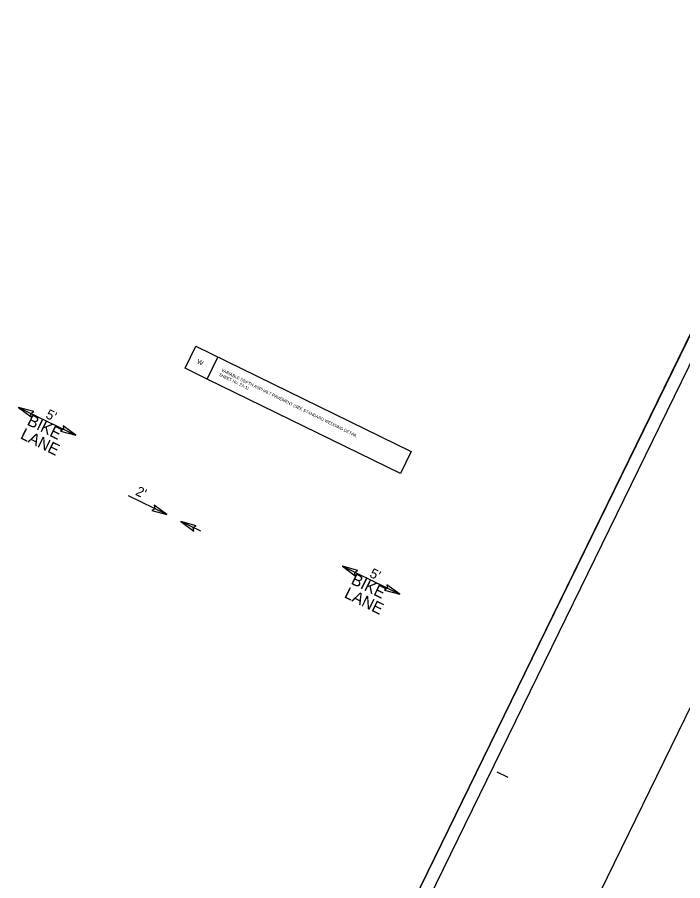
# Model space of a CAD drawing. Extents: x 1518247 to 1523638, y 635234 to 639927.
# Drawn here: x 1520564 to 1521243, y 639046 to 639927 of the extents above; entities that cross this region are included whole.
import ezdxf

# ---------------------------------------------------------------- set-up
doc = ezdxf.new("R2010")
doc.units = 0
for name, color, linetype in [('Default', 7, 'Continuous'), ('Prop Dimension', 7, 'Continuous'), ('Prop Pavement Schedule Description CELL', 7, 'Continuous'), ('Prop Shade Light', 7, 'Continuous'), ('Sheet Cutting Line CELL', 7, 'Continuous'), ('Sheet Plot Border Inside CELL', 7, 'Continuous'), ('Sheet Plot Border Outside CELL', 7, 'Continuous'), ('Sheet Typical CELL', 7, 'Continuous')]:
    doc.layers.add(name, color=color, linetype=linetype)

# ---------------------------------------------------------------- blocks, each defined once
blk = doc.blocks.new('TERMINATOR')
at = {"layer": 'Prop Shade Light'}
blk.add_lwpolyline([(-0.469, 0.081), (0, 0), (-0.471, -0.083), (-0.411, 0)], close=True, dxfattribs=at)

msp = doc.modelspace()

# ---------------------------------------------------------------- linework, layer by layer
at = {"layer": 'Default'}
msp.add_lwpolyline([(1522438.02, 638198.63), (1520925.25, 638938.49), (1521408.53, 639926.64), (1522921.3, 639186.78)], close=True, dxfattribs=at)
at = {"layer": 'Prop Dimension'}
for p, q in [((1520564.84, 639528.91), (1520623.22, 639500.41)), ((1520716.24, 639419.51), (1520676.94, 639438.69)), ((1520750.88, 639402.6), (1520730.57, 639412.51)), ((1520895.42, 639366.83), (1520953.79, 639338.33))]:
    msp.add_line(p, q, dxfattribs=at)
at = {"layer": 'Prop Pavement Schedule Description CELL'}
msp.add_lwpolyline([(1520757.32, 639557.78), (1520734.87, 639568.76), (1520745.85, 639591.22), (1520965.45, 639483.82), (1520954.46, 639461.36), (1520757.32, 639557.78), (1520768.31, 639580.23)], dxfattribs=at)
at = {"layer": 'Sheet Cutting Line CELL'}
msp.add_line((1521408.53, 639926.64), (1520925.25, 638938.49), dxfattribs=at)
at = {"layer": 'Sheet Plot Border Inside CELL'}
msp.add_lwpolyline([(1522907.39, 639168.59), (1521410.35, 639900.76), (1520946.79, 638952.95), (1522443.84, 638220.77)], close=True, dxfattribs=at)
at = {"layer": 'Sheet Plot Border Outside CELL'}
msp.add_lwpolyline([(1522921.3, 639186.78), (1521408.53, 639926.64), (1520925.25, 638938.49), (1522438.02, 638198.63)], close=True, dxfattribs=at)
at = {"layer": 'Sheet Typical CELL'}
msp.add_line((1521052.8, 639157.19), (1521064.03, 639151.7), dxfattribs=at)
msp.add_lwpolyline([(1522895.04, 639171.79), (1521547.57, 639830.81), (1521086.25, 638887.58), (1522433.73, 638228.56)], close=True, dxfattribs=at)

# ---------------------------------------------------------------- block references
at = {"layer": 'Prop Dimension', "xscale": 33.82820784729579, "yscale": -36.41552511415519}
for p, rotation in [((1520564.84, 639528.91), 153.97926941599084), ((1520623.22, 639500.41), -26.020730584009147), ((1520716.24, 639419.51), -26.020730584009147), ((1520730.57, 639412.51), 153.97926941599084), ((1520895.42, 639366.83), 153.97926941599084), ((1520953.79, 639338.33), -26.020730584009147)]:
    msp.add_blockref('TERMINATOR', p, dxfattribs=dict(at, rotation=rotation))

# ---------------------------------------------------------------- texts
at = {"layer": 'Prop Dimension'}
for s, height, rotation, p in [('BIKE', 11.865, 333.74084, (1520572.65, 639511.53)), ("5'", 9.969, 333.97927, (1520591.67, 639518.5)), ('LANE', 11.865, 333.74084, (1520565.77, 639497.58)), ("2'", 9.969, 333.97927, (1520683.41, 639440.05)), ("5'", 9.969, 333.97927, (1520922.25, 639356.42)), ('BIKE', 11.865, 333.74084, (1520903.23, 639349.45)), ('LANE', 11.865, 333.74084, (1520896.34, 639335.5))]:
    msp.add_text(s, height=height, rotation=rotation, dxfattribs=at).set_placement(p)
at = {"layer": 'Prop Pavement Schedule Description CELL'}
for s, height, p in [('W ', 4.889, (1520746.32, 639574.1)), ('VARIABLE DEPTH ASPHALT PAVEMENT (SEE STANDARD WEDGING DETAIL', 3.0556, (1520771.2, 639565.87)), ('SHEET No. 2A-1)', 3.0556, (1520769.01, 639561.39))]:
    msp.add_text(s, height=height, rotation=333.93772, dxfattribs=at).set_placement(p)

doc.saveas('drawing.dxf')
